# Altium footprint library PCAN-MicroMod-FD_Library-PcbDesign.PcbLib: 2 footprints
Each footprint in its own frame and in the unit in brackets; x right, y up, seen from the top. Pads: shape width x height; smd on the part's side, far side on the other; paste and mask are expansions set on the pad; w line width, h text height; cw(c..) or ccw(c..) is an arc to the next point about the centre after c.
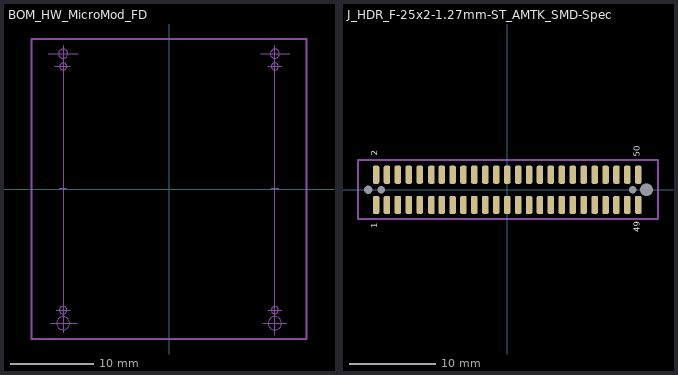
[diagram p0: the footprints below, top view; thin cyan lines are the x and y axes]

## BOM_HW_MicroMod_FD [mm]
height 10
pads (100):
  rrect50% 2.1x0.76 on Mech15: A1(-14.45,15.316) B1(10.95,15.316)
  oct 2.1x0.76 on Mech15: A2(-10.95,15.316) A3(-14.45,14.046) A4(-10.95,14.046) A5(-14.45,12.776) A6(-10.95,12.776) A7(-14.45,11.506) A8(-10.95,11.506) A9(-14.45,10.236) A10(-10.95,10.236) A11(-14.45,8.876) A12(-10.95,8.876) A13(-14.45,7.696) A14(-10.95,7.696) A15(-14.45,6.426) A16(-10.95,6.426) A17(-14.45,5.156) A18(-10.95,5.156) A19(-14.45,3.886) A20(-10.95,3.886) A21(-14.45,2.616) A22(-10.95,2.616) A23(-14.45,1.346) A24(-10.95,1.346) A25(-14.45,0.076) A26(-10.95,0.076) A27(-14.45,-1.194) A28(-10.95,-1.194) A29(-14.45,-2.464) A30(-10.95,-2.464) A31(-14.45,-3.734) A32(-10.95,-3.734) A33(-14.45,-5.004) A34(-10.95,-5.004) A35(-14.45,-6.274) A36(-10.95,-6.274) A37(-14.45,-7.544) A38(-10.95,-7.544) A39(-14.45,-8.814) A40(-10.95,-8.814) A41(-14.45,-10.084) A42(-10.95,-10.084) A43(-14.45,-11.354) A44(-10.95,-11.354) A45(-14.45,-12.624) A46(-10.95,-12.624) A47(-14.45,-13.894) A48(-10.95,-13.894) A49(-14.45,-15.164) A50(-10.95,-15.164) B2(14.45,15.316) B3(10.95,14.046) B4(14.45,14.046) B5(10.95,12.776) B6(14.45,12.776) B7(10.95,11.506) B8(14.45,11.506) B9(10.95,10.236) B10(14.45,10.236) B11(10.95,8.966) B12(14.45,8.966) B13(10.95,7.696) B14(14.45,7.696) B15(10.95,6.426) B16(14.45,6.426) B17(10.95,5.156) B18(14.45,5.156) B19(10.95,3.886) B20(14.45,3.886) B21(10.95,2.616) B22(14.45,2.616) B23(10.95,1.346) B24(14.45,1.346) B25(10.95,0.076) B26(14.45,0.076) B27(10.95,-1.194) B28(14.45,-1.194) B29(10.95,-2.464) B30(14.45,-2.464) B31(10.95,-3.734) B32(14.45,-3.734) B33(10.95,-5.004) B34(14.45,-5.004) B35(10.95,-6.274) B36(14.45,-6.274) B37(10.95,-7.544) B38(14.45,-7.544) B39(10.95,-8.814) B40(14.45,-8.814) B41(10.95,-10.084) B42(14.45,-10.084) B43(10.95,-11.354) B44(14.45,-11.354) B45(10.95,-12.624) B46(14.45,-12.624) B47(10.95,-13.894) B48(14.45,-13.894) B49(10.95,-15.164) B50(14.45,-15.164)
Mechanical 10:
  lines w0.254: -16.5,-18 16.5,-18 16.5,18 -16.5,18 -16.5,-18
Mechanical 15:
  circle w0.1: c-12.7,14.701 r0.426
  circle w0.1: c-12.7,-14.524 r0.451
  circle w0.1: c-12.7,-16.114 r0.78
  circle w0.1: c-12.7,16.236 r0.55
  circle w0.1: c12.7,14.701 r0.426
  circle w0.1: c12.7,-14.524 r0.431
  circle w0.1: c12.7,-16.114 r0.801
  circle w0.1: c12.7,16.236 r0.55
  lines w0.051: -14.478,16.236 -10.922,16.236 ; -14.2,-16.114 -11,-16.114 ; -13.725,14.701 -11.85,14.701 ; -13.55,-14.524 -11.875,-14.524 ; -13.125,0.076 -12.25,0.076 ; -12.7,-17.272 -12.7,17.272 ; 11,16.236 14.5,16.236 ; 11.225,-16.114 14.125,-16.114 ; 11.825,14.701 13.525,14.701 ; 11.875,-14.524 13.525,-14.524 ; 12.25,0.076 13.175,0.076 ; 12.7,-17.526 12.7,17.272
  text "50" at -9.475,-15.525 h1
  text "2" at -9.425,14.975 h1
  text "A" at -13.125,-18.525 h1.5
  text "A" at -13.2,17.725 h1.5
  text "49" at -16.8,-15.475 h1
  text "1" at -16.425,14.9 h1
  text "49" at 8.45,-15.475 h1
  text "1" at 8.8,15 h1
  text "B" at 12.475,-18.65 h1.5
  text "B" at 12.3,17.875 h1.5
  text "50" at 15.925,-15.475 h1
  text "2" at 15.925,15.1 h1
3D body "MicroModFD_v4.step": height 11.62, standoff 0.91, extent -16.5,-18.034 16.5,17.966

## J_HDR_F-25x2-1.27mm-ST_AMTK_SMD-Spec [mm]
height 4.85
pads (54):
  rrect50% 0.76x2.1 smd: 1(-15.255,-1.75) 2(-15.255,1.75) 3(-13.985,-1.75) 4(-13.985,1.75) 5(-12.715,-1.75) 6(-12.715,1.75) 7(-11.445,-1.75) 8(-11.445,1.75) 9(-10.175,-1.75) 10(-10.175,1.75) 11(-8.815,-1.75) 12(-8.815,1.75) 13(-7.635,-1.75) 14(-7.635,1.75) 15(-6.365,-1.75) 16(-6.365,1.75) 17(-5.095,-1.75) 18(-5.095,1.75) 19(-3.825,-1.75) 20(-3.825,1.75) 21(-2.555,-1.75) 22(-2.555,1.75) 23(-1.285,-1.75) 24(-1.285,1.75) 25(-0.015,-1.75) 26(-0.015,1.75) 27(1.255,-1.75) 28(1.255,1.75) 29(2.525,-1.75) 30(2.525,1.75) 31(3.795,-1.75) 32(3.795,1.75) 33(5.065,-1.75) 34(5.065,1.75) 35(6.335,-1.75) 36(6.335,1.75) 37(7.605,-1.75) 38(7.605,1.75) 39(8.875,-1.75) 40(8.875,1.75) 41(10.145,-1.75) 42(10.145,1.75) 43(11.415,-1.75) 44(11.415,1.75) 45(12.685,-1.75) 46(12.685,1.75) 47(13.955,-1.75) 48(13.955,1.75) 49(15.225,-1.75) 50(15.225,1.75)
  round 0 hole 0.9 unplated: H1(-14.64,0) H2(14.585,0)
  round 0 hole 1 unplated: H3(-16.175,0)
  round 0 hole 1.5 unplated: H4(16.175,0)
Top Overlay:
  text "50" at 15.6,3.825 h1.2
  text "49" at 15.621,-4.953 h1.2
  text "2" at -14.859,3.937 h1.2
  text "1" at -14.859,-4.445 h1.2
Mechanical 10:
  lines w0.254: -17.35,-3.4 -17.35,3.475 17.511,3.475 17.511,-3.4 -17.35,-3.4
3D body "J_HDR_F-25x2-1.27mm-ST_AMTK_SMD-Spec.stp": height 4.6, standoff -1, extent -17.625,-2.3 17.625,2.3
